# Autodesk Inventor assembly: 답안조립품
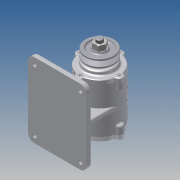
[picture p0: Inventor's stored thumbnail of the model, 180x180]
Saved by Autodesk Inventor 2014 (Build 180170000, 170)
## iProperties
Created: 2015-12
Part Number: 답안조립품
Document SubType Name: Assembly
Designer: Owner
Author: Owner
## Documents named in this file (11)
- C:\Documents and Settings\Owner\바탕 화면\451207V1005\답안조립품.iam
- C:\Documents and Settings\Owner\바탕 화면\451207V1005\본체.ipt
- C:\Documents and Settings\Owner\바탕 화면\451207V1005\커버2.ipt
- C:\Documents and Settings\Owner\바탕 화면\451207V1005\볼트 M4 x 12.ipt
- C:\Documents and Settings\Owner\바탕 화면\451207V1005\커버.ipt
- C:\Documents and Settings\Owner\바탕 화면\451207V1005\오일실.ipt
- C:\Documents and Settings\Owner\바탕 화면\451207V1005\베어링 6204.ipt
- C:\Documents and Settings\Owner\바탕 화면\451207V1005\축.ipt
- C:\Documents and Settings\Owner\바탕 화면\451207V1005\키(4 x 4 x 12).ipt
- C:\Documents and Settings\Owner\바탕 화면\451207V1005\V-벨트풀리.ipt
- C:\Documents and Settings\Owner\바탕 화면\451207V1005\너트 M12x1.25.ipt
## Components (6 placed, 5 different names)
1. KS B 2804 D D - 20 32 8:1
2. KS B 2023 6204 - 20 x 47 x 14:1
3. KS B 2023 6204 - 20 x 47 x 14:2
4. KS B 1311 (I) 4 x 4 x 12:1
5. V-벨트풀리:1
6. KS B 1012 클래스 1 일반 - 미터 M12x1.25:1
